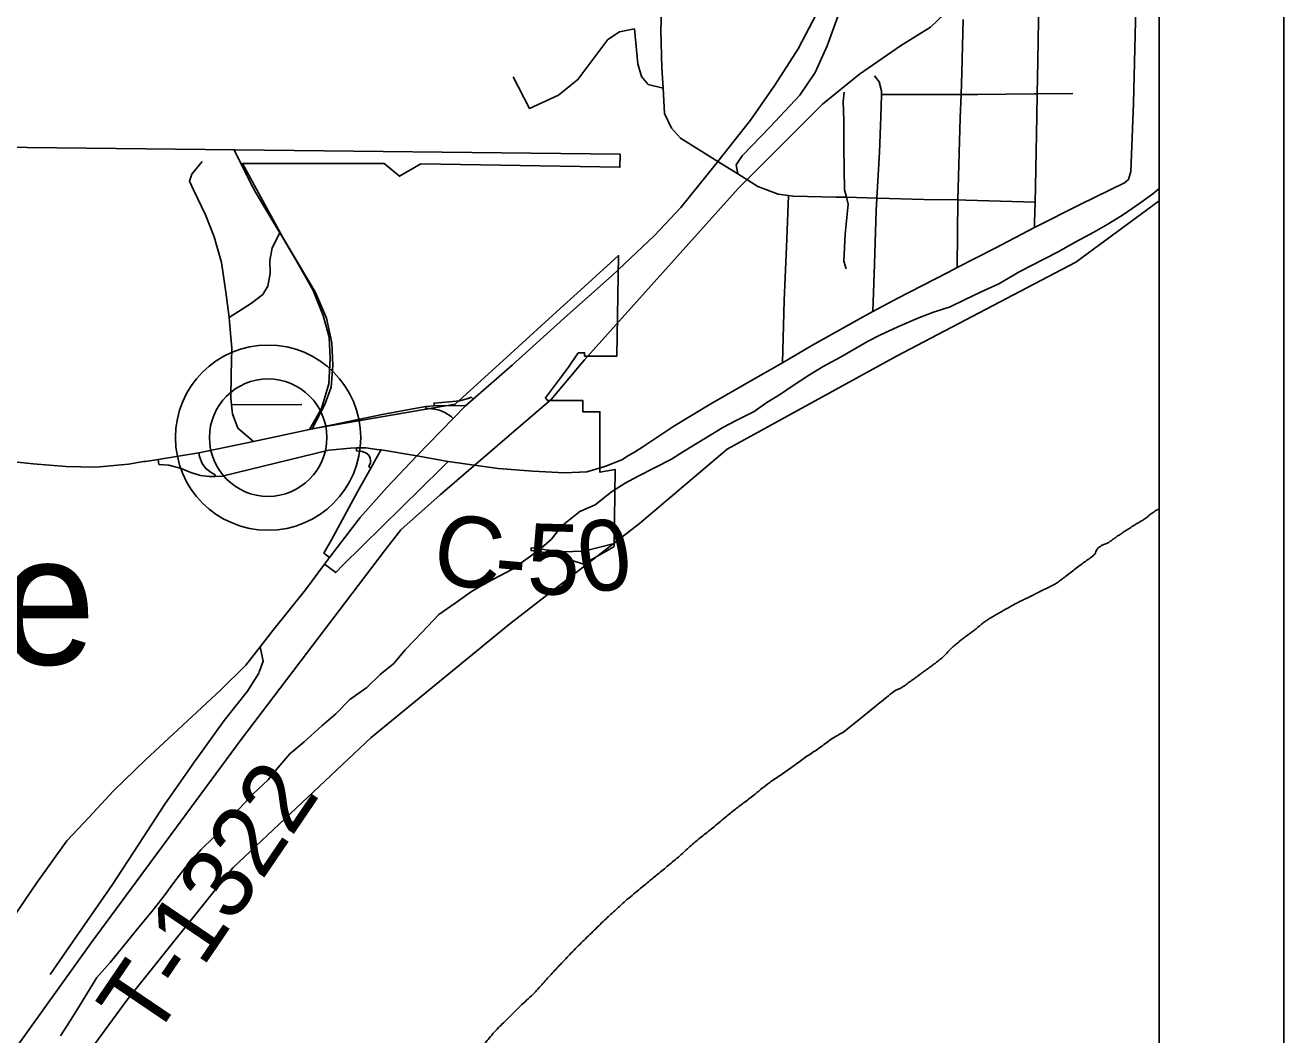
# Model space of a CAD drawing. Extents: x -84548 to 2262448, y -162180 to 525962.
# Drawn here: x 42243 to 47579, y 95098 to 99380 of the extents above; entities that cross this region are included whole.
import ezdxf

# ---------------------------------------------------------------- set-up
doc = ezdxf.new("R2010")
doc.units = 0
for name, color, linetype in [('GM_X_Adjacent_County_Text', 7, 'Continuous'), ('GM_X_County', 7, 'Continuous'), ('GM_X_County_Road', 7, 'Continuous'), ('GM_X_Hydro', 7, 'Continuous'), ('GM_X_Hydro_Text', 7, 'Continuous'), ('GM_X_Interstate_Location', 7, 'Continuous'), ('GM_X_Major_Lake_Text', 7, 'Continuous'), ('GM_X_Major_River', 7, 'Continuous'), ('GM_X_Minor_Lake', 7, 'Continuous'), ('GM_X_Minor_River_Text', 7, 'Continuous'), ('GM_X_Township_Road', 7, 'Continuous'), ('GM_X_Township_ROW', 7, 'Continuous'), ('GM_X_Township_Subdivision_Text', 7, 'Continuous'), ('GM_X_Unincorporated_Location', 7, 'Continuous'), ('GM_X_US_Location', 7, 'Continuous')]:
    doc.layers.add(name, color=color, linetype=linetype)

msp = doc.modelspace()

# ---------------------------------------------------------------- linework, layer by layer
at = {"layer": 'GM_X_County'}
for p, q in [((47578.7, 110848.8), (47578.7, 73888.8)), ((47050.7, 110320.8), (47050.7, 74416.8))]:
    msp.add_line(p, q, dxfattribs=at)
at = {"layer": 'GM_X_Hydro'}
for p, q in [((46697.6, 98375.1), (47050.7, 98634.4)), ((45936.2, 97976.2), (46697.6, 98375.1)), ((45218.9, 97582.1), (45936.2, 97976.2)), ((44847.3, 97266.3), (45218.9, 97582.1)), ((44297.1, 96841), (44847.3, 97266.3)), ((43709.8, 96358.8), (44297.1, 96841)), ((43123.7, 95806.4), (43709.8, 96358.8)), ((42676.3, 95246.3), (43123.7, 95806.4)), ((42168.9, 94556.7), (42676.3, 95246.3))]:
    msp.add_line(p, q, dxfattribs=at)
at = {"layer": 'GM_X_Hydro_Text'}
for points in [[(44142.4, 97793.9), (44133.4, 97802.5), (44117.5, 97795.1), (44084.5, 97787.3), (44042.6, 97782.3), (43976.8, 97776.9), (43977.6, 97765.4)], [(43941.2, 97762), (43941.5, 97755.2), (43978.8, 97751.7), (43999.5, 97746.6), (44022.6, 97737.2), (44048.4, 97720.7), (44058, 97711.3)], [(42806.8, 97538.1), (42810.1, 97516.9), (42852.8, 97514.5), (42904, 97500.3), (42945.7, 97483), (42986.5, 97470.6), (43023.3, 97465.1), (43048.8, 97466), (43077.8, 97466.9), (43531.2, 97578), (43622, 97586.6), (43648.4, 97586.7), (43687.8, 97586.9), (43744.2, 97579.3), (43752.1, 97578.2)], [(43648.4, 97586.7), (43648.3, 97574.2), (43672.3, 97572), (43687, 97566.6), (43700.1, 97556.2), (43705.6, 97544.2), (43707, 97534.5), (43706.6, 97523.5), (43700.4, 97508), (43709.1, 97501.7)], [(42979.5, 97566.6), (42982.2, 97550.2), (42993.2, 97520.5), (43008.9, 97499.3), (43031.4, 97482.1), (43048.6, 97472.7), (43048.8, 97466)], [(43752.1, 97578.2), (43743.5, 97565.4), (43724.6, 97529.3), (43709.1, 97501.7), (43653.7, 97402.9), (43541.7, 97197.2), (43509.2, 97140.9), (43533.7, 97122.8)], [(43512, 97093.5), (43559.6, 97058.3), (43589.5, 97089.2), (44006.8, 97499.3), (44037, 97530.1)]]:
    msp.add_lwpolyline(points, dxfattribs=at)
at = {"layer": 'GM_X_Interstate_Location'}
for points in [[(47050.7, 98686.8), (47023.5, 98665.1), (46972, 98628.2), (46898.8, 98576.9), (46833.3, 98535.7), (46773.8, 98502.6), (46696.4, 98461.3), (46619, 98417.9), (46460.1, 98335.1), (46370.8, 98283.5), (46293.3, 98248.2), (46227.7, 98217), (46164.1, 98185.9), (46094.4, 98162.7), (46034.7, 98139.7), (45943.2, 98100.1), (45865.7, 98064.7), (45814.1, 98037.8), (45699, 97971.8), (45625.5, 97932.5), (45568, 97897.4), (45498.7, 97852.2), (45445.2, 97815.2), (45387.7, 97780.2), (45334.2, 97741.2), (45256.7, 97703.9), (45201.2, 97672.9), (45131.7, 97631.6), (45034.6, 97571.9), (44983, 97538.9), (44913.5, 97503.7), (44842, 97466.5), (44786.4, 97437.5)], [(44786.4, 97437.5), (44728.9, 97400.4), (44659.7, 97345.2), (44594.1, 97318), (44517, 97254.6), (44473.8, 97199.7), (44420.5, 97152.7), (44365.1, 97113.7), (44309.7, 97072.7), (44198.5, 97014.7), (44135, 96977.6), (44065.7, 96928.3), (43996.4, 96881.1), (43925.5, 96805.7), (43854.6, 96730.4), (43805.4, 96673.4), (43748.1, 96626.3), (43690.9, 96571.2), (43619.7, 96519.9), (43560.6, 96458.8), (43501.3, 96407.7), (43426.3, 96340.3), (43365, 96289.1), (43313.9, 96230.1), (43272.7, 96179.3), (43209.5, 96120.1), (43150.5, 96057), (43075.5, 95989.6), (43044.3, 95936.9), (42989.1, 95883.9), (42922.2, 95806.5), (42873.2, 95743.6), (42832, 95686.7), (42781, 95621.7), (42731.9, 95562.7), (42604.2, 95404.2), (42547.2, 95341.1), (42516, 95290.4), (42473, 95221.5), (42434, 95156.7), (42392.9, 95093.9)]]:
    msp.add_lwpolyline(points, dxfattribs=at)
msp.add_open_spline([(45712.5, 96382.1), (45781, 96437.3), (45849.4, 96492.5), (45917.8, 96547.7), (45933.4, 96560.2), (45953.5, 96566.3), (45969.7, 96578), (45988.4, 96591.4), (46007, 96604.9), (46025.6, 96618.5), (46044.9, 96632.6), (46064.2, 96646.7), (46083.4, 96660.9), (46096.9, 96670.8), (46110.2, 96680.8), (46123.3, 96691.2), (46142.9, 96706.8), (46158.2, 96727.2), (46177.1, 96743.6), (46191.4, 96756.1), (46205.9, 96768.4), (46220.9, 96780), (46236.1, 96791.6), (46251.6, 96802.8), (46266.8, 96814.3), (46282.3, 96826.2), (46296.8, 96839.3), (46312.7, 96850.7), (46326, 96860.4), (46340.3, 96868.7), (46354.6, 96877), (46369.8, 96885.9), (46385.1, 96894.7), (46400.5, 96903.3), (46416.4, 96912.3), (46432.2, 96921.3), (46448.4, 96929.7), (46466.2, 96938.8), (46484.4, 96947), (46502.3, 96956), (46517, 96963.4), (46531.6, 96970.9), (46546.3, 96978.3), (46561.4, 96986), (46577.1, 96992.8), (46592.2, 97000.7), (46610.6, 97010.2), (46627.4, 97022.6), (46644.1, 97035), (46666.2, 97051.6), (46687.9, 97068.9), (46709.9, 97085.6), (46728.2, 97099.4), (46747.3, 97112.2), (46765.7, 97126), (46780.1, 97136.8), (46784.8, 97157.8), (46799.5, 97168.3), (46811.7, 97177), (46827.2, 97180.1), (46839.5, 97188.6), (46852.9, 97197.8), (46865.8, 97207.9), (46879.4, 97216.9), (46897.9, 97229.1), (46916.5, 97241.3), (46935.2, 97253.3), (46951.6, 97263.7), (46968.7, 97273.2), (46985.1, 97283.6), (47000.4, 97293.4), (47013.8, 97306), (47029, 97316), (47036, 97320.6), (47043.4, 97324.8), (47050.7, 97329)], degree=3, dxfattribs=at)
for points in [[(44891, 95751.7), (44930.9, 95784), (44974.7, 95820.4), (45024.5, 95862.8), (45066.4, 95901.1), (45110.2, 95937.4), (45158.1, 95975.8), (45211.9, 96020.3), (45253.8, 96054.6), (45293.6, 96084.9), (45337.5, 96119.2), (45399.3, 96167.7), (45443.2, 96198), (45523, 96254.6), (45568.9, 96287), (45616.7, 96319.3), (45666.6, 96355.7), (45712.5, 96382.1)], [(41241, 91094), (41262.8, 91144.3), (41286.6, 91184.6), (41320.3, 91228.9), (41360.1, 91271.2), (41381.9, 91311.4), (41421.8, 91349.8), (41445.6, 91394), (41481.3, 91454.4), (41497, 91494.6), (41530.8, 91544.9), (41582.5, 91605.4), (41616.3, 91645.7), (41672.1, 91698.2), (41715.9, 91744.5), (41743.7, 91788.8), (41785.4, 91837.2), (41821.2, 91883.5), (41847, 91927.8), (41906.6, 92018.4), (41944.3, 92076.8), (41976, 92131.1), (42005.7, 92183.4), (42027.5, 92223.7), (42057.3, 92276), (42081, 92318.2), (42106.8, 92360.5), (42136.6, 92414.8), (42196.1, 92515.4), (42225.8, 92563.7), (42253.6, 92606), (42287.3, 92658.4), (42315.1, 92698.6), (42336.9, 92740.9), (42370.7, 92789.2), (42400.5, 92831.5), (42434.2, 92889.8), (42470, 92940.2), (42507.7, 92996.6), (42543.4, 93044.9), (42575.2, 93089.2), (42607, 93131.5), (42636.8, 93173.8), (42664.6, 93216.1), (42692.4, 93256.3), (42726.2, 93302.7), (42754, 93342.9), (42793.7, 93401.3), (42823.5, 93441.6), (42855.3, 93481.9), (42891.1, 93522.2), (42926.9, 93572.5), (42974.7, 93627), (43008.4, 93669.3), (43048.2, 93723.7), (43087.9, 93774), (43153.5, 93862.6), (43185.3, 93906.9), (43231, 93965.4), (43266.8, 94009.7), (43316.6, 94068.1), (43358.3, 94114.5), (43410.1, 94171), (43449.9, 94213.3), (43479.7, 94253.6), (43521.6, 94277.9), (43563.5, 94318.2), (43611.3, 94354.6), (43653.2, 94392.9), (43720.8, 94463.5), (43764.7, 94499.9), (43808.5, 94550.3), (43852.2, 94604.7), (43884, 94653), (43929.6, 94721.4), (43967.4, 94769.8), (44033, 94858.4), (44076.7, 94910.8), (44110.5, 94955.1), (44140.3, 95001.4), (44176.1, 95041.7), (44209.9, 95084), (44255.7, 95134.4), (44295.5, 95172.7), (44335.3, 95213.1), (44389.1, 95263.5), (44432.9, 95309.9), (44472.7, 95354.2), (44512.5, 95396.6), (44558.3, 95445), (44606.1, 95493.4), (44655.9, 95541.8), (44705.7, 95590.2), (44747.5, 95628.6), (44787.3, 95664.9), (44845.1, 95713.3), (44891, 95751.7)]]:
    msp.add_spline(points, degree=3, dxfattribs=at)
at = {"layer": 'GM_X_Major_Lake_Text'}
for points in [[(44753.8, 98339.4), (44758.6, 98344), (44911.4, 98487.2), (45022.5, 98606.2), (45175.1, 98795.6), (45180.1, 98802), (45317.8, 98977), (45420.7, 99126), (45519.5, 99278.9), (45598.4, 99427.8), (45667, 99612.5), (45715.7, 99785.2), (45745.2, 99967.9), (45748.1, 99985.7), (45762.3, 100212.1), (45762.7, 100249), (45764.6, 100424.5), (45749.3, 100596.6), (45721.6, 100806.7), (45706.3, 100964.8), (45706, 100978), (45704.2, 101052.1), (45703.4, 101084.9), (45708.6, 101141.4)], [(44110.5, 97766), (44142.4, 97793.9), (44307.3, 97937.8), (44527.9, 98137.7), (44732.6, 98319.6), (44753.8, 98339.4)], [(41208.8, 97945.8), (41265.3, 97920.3), (41411.8, 97836.8), (41808.8, 97639.7), (41965.4, 97584.6), (42114.8, 97536.4), (42277.1, 97519.6), (42415.2, 97508.7), (42543.4, 97505.6), (42681.4, 97518.7), (42745.6, 97528.7), (42752.8, 97529.8)], [(42752.8, 97529.8), (42806.8, 97538.1), (42979.5, 97566.6), (43211.6, 97614.3), (43448.8, 97664.9), (43546.7, 97685.6), (43756.5, 97729.3), (43902.3, 97756.2), (43941.2, 97762), (43977.6, 97765.4), (44022.7, 97767.1), (44110.5, 97766)], [(43903.5, 97552.9), (44058, 97711.3), (44110.5, 97766)], [(43533.7, 97122.8), (43663.9, 97291.9), (43777, 97419), (43903.5, 97552.9)], [(43752.1, 97578.2), (43903.5, 97552.9), (44037, 97530.1)], [(41071.1, 93788.6), (41225.8, 94062.6), (41280.6, 94211.2), (41333.8, 94321.8), (41424.8, 94460.7), (41543.4, 94639.8), (41691.8, 94857.3), (41848.1, 95080.8), (41984.6, 95286.2), (42134.9, 95511.6), (42291.2, 95741.2), (42419.9, 95920.4), (42515.2, 96021.3), (42618.4, 96132.2), (42753.4, 96263.5), (42892.5, 96392.7), (43071.3, 96560.3), (43178.5, 96665.3), (43239.9, 96743.9), (43293.5, 96812.4), (43432.2, 96985.7), (43512, 97093.5), (43533.7, 97122.8)]]:
    msp.add_lwpolyline(points, dxfattribs=at)
at = {"layer": 'GM_X_Major_River'}
for radius in [392.8, 249]:
    msp.add_circle((43273.2, 97630.6), radius, dxfattribs=at)
at = {"layer": 'GM_X_Minor_Lake'}
for points in [[(43236.4, 96639.8), (43251.5, 96682.5), (43239.9, 96743.9)], [(42954.1, 96246.3), (42955.3, 96247.9), (42967.9, 96265.9), (43087, 96431), (43186.2, 96555.9), (43233.8, 96632.3), (43235.7, 96637.9), (43236.4, 96639.8)], [(42472.4, 95531.3), (42473.4, 95532.9), (42492.1, 95559.6), (42613, 95734.7), (42722.1, 95901.7), (42835, 96076.8), (42954.1, 96246.3)], [(42349.3, 95354.4), (42472.4, 95531.3)]]:
    msp.add_lwpolyline(points, dxfattribs=at)
at = {"layer": 'GM_X_Minor_River_Text'}
msp.add_lwpolyline([(44037, 97530.1), (44249, 97499.9), (44395.3, 97489), (44529.5, 97481.8), (44623.5, 97485.8), (44701.1, 97507.5), (44772.5, 97537), (44801.5, 97554.7)], dxfattribs=at)
at = {"layer": 'GM_X_Township_ROW'}
for points in [[(43215.8, 98679.5), (43200.6, 98705.6), (43129.7, 98850.7)], [(43108.7, 98139.9), (43093.9, 98248), (43075, 98374.1), (43044.2, 98482.1), (43007.5, 98576.1), (42956.7, 98681.9), (42940.5, 98717.9), (42950.2, 98748), (42993.9, 98802.4)], [(43448.8, 97664.9), (43499.7, 97753.8), (43531, 97858.2), (43536.2, 97966.4), (43531.5, 98056.5), (43506.8, 98148.5), (43464, 98254.5), (43401.2, 98368.3), (43338.4, 98474), (43323.2, 98499), (43271.6, 98583.8), (43216, 98679.2), (43215.8, 98679.5)], [(43211.6, 97614.3), (43144.2, 97671.3), (43121.7, 97731.3), (43118.1, 97769.2), (43115.2, 97799.4), (43116.5, 97897.5), (43119.7, 98009.8), (43113.2, 98071.8), (43108.7, 98139.9), (43202.3, 98200.7), (43250.1, 98237), (43271.8, 98273.2), (43281.4, 98327.4), (43281, 98381.5), (43290.6, 98435.7), (43323.2, 98499)], [(43118.1, 97769.2), (43415.5, 97771.3)]]:
    msp.add_lwpolyline(points, dxfattribs=at)
at = {"layer": 'GM_X_Township_Subdivision_Text'}
msp.add_lwpolyline([(41246.2, 98871.8), (44765.1, 98832.4), (44764.3, 98777.3), (43920.6, 98791.4), (43830, 98739), (43764.9, 98793.7), (43164.9, 98793.6), (43335.8, 98479.4), (43474.6, 98246.1), (43520, 98137.7), (43543.5, 98033.3), (43546.9, 97937.1), (43540.4, 97844.9), (43513.9, 97770.9), (43460.4, 97668.6), (43720.6, 97713.5), (44066, 97773), (44300.4, 97986.1), (44495.8, 98163.7), (44613.1, 98270.3), (44758.5, 98402.5), (44751.8, 97976.8), (44614.5, 97976.8), (44614.5, 97990.3), (44587.5, 97990.3), (44546.1, 97928.9), (44448.6, 97799.5), (44457.9, 97788.4), (44607.1, 97788.4), (44607.1, 97740.4), (44679.5, 97740.4), (44679.5, 97483.5), (44744.4, 97495.1), (44739.5, 97181.2), (44613.3, 97149), (44516.4, 97146), (44388.6, 97163.9), (44387.8, 97151.9), (44466, 97141), (44610.6, 97094), (44738.7, 97168), (44741.5, 97184.5), (44847.3, 97266.3), (45218.9, 97582.1), (45936.2, 97976.2), (46697.6, 98375.1), (47050.7, 98634.4), (47050.7, 109898.9)], dxfattribs=at)
at = {"layer": 'GM_X_Unincorporated_Location'}
for points in [[(45953.6, 99292.7), (46081.1, 99371.1), (46197.6, 99483.5), (46263.1, 99609.1), (46272, 99663.5), (46320, 101325.8), (46287.9, 101405.9), (46163.8, 101688.7), (46110.4, 101854), (46059.5, 102031), (46017.3, 102132.8), (45944.3, 102204.4), (44999.2, 103131.7), (44132.9, 103939.2)], [(40921.8, 93255), (42522.6, 95488.3), (43158.2, 96349.8), (43766.5, 97151), (43836.3, 97239.1), (44001.9, 97387.6), (44365.8, 97699.9), (44473.2, 97792.2), (44613.7, 97960.7), (45265, 98686.9), (45623.6, 99044.3), (45780.2, 99172.7), (45953.6, 99292.7)]]:
    msp.add_lwpolyline(points, dxfattribs=at)
at = {"layer": 'GM_X_US_Location'}
for points in [[(45264.9, 98749.2), (45180.1, 98802), (45021.1, 98901.1), (44982.6, 98942.8), (44953.9, 99004.7), (44947.3, 99112.6), (44941.9, 99199), (44938.3, 99357.2), (44941.4, 99439.4), (44966.4, 99543.9), (45028.3, 99752.9), (45078.6, 99919.7), (45109.2, 100054.3), (45137.7, 100206.9), (45148.3, 100337.3), (45152.9, 100475.6), (45141.7, 100593.7), (45122.5, 100705.8), (45081.1, 100837.6), (45023.7, 100971.3), (44974.8, 101049)], [(46522, 98525.8), (46522.4, 98542.5), (46524.6, 98629), (46526.2, 98694), (46531.7, 98994.6), (46533.7, 99088.2), (46536.6, 99227.1), (46539.3, 99400.5), (46540, 99441.5), (46544.7, 99686), (46545.7, 99731.4), (46549.8, 99912.4), (46549.6, 100090.2), (46549.6, 100102.7), (46560.1, 100451.5), (46568.8, 100788.2), (46597.1, 100787.4)], [(46920.6, 98725.3), (46930.2, 98759.4), (46941.2, 99048.1), (46949.7, 99397), (46958.8, 99669.5), (46966.6, 99890), (46973.9, 100077.5), (46977.7, 100172.7), (46988.1, 100515.5), (47050.7, 100643.8)], [(45264.9, 98749.2), (45256.5, 98787.2), (45282.1, 98825.5), (45400.9, 98948.9), (45527.6, 99082.4), (45592.7, 99179.3), (45643.6, 99292), (45687.7, 99416.2), (45692.2, 99428.7), (45734.5, 99597.5), (45775, 99746.2)], [(46194.4, 98352.1), (46196.8, 98638.8), (46207.2, 98986.9), (46210.3, 99085.8), (46213.2, 99179.3), (46218.9, 99404.5)], [(44311.8, 99160.7), (44381.2, 99027.1), (44504.7, 99082.5), (44586.1, 99149.4), (44649.3, 99234.2), (44712.5, 99319), (44762.2, 99351.5), (44826.1, 99364.2), (44839.7, 99216), (44856.2, 99162.1), (44884.6, 99128.3), (44947.3, 99112.6)], [(45870.7, 98993.8), (45872.4, 99035.7), (45873.4, 99085.9), (45873.7, 99101.8), (45863.3, 99139.8), (45843.1, 99165.7)], [(45720.2, 98666.1), (45720.1, 98666.5), (45716, 98681.5), (45714.1, 98861.8), (45712.9, 98976), (45710.1, 99056.2), (45715.7, 99096.3)], [(45873.4, 99085.9), (46090.1, 99085.9), (46210.3, 99085.8), (46282.3, 99085.8), (46522.5, 99088.1), (46533.7, 99088.2), (46684.6, 99089.7)], [(45836.7, 98165.1), (45843.3, 98366.1), (45851, 98594.6), (45853.8, 98646.8), (45864.4, 98841.2), (45870.6, 98990.5), (45870.7, 98993.8)], [(45264.9, 98749.2), (45349.5, 98695.9), (45435.9, 98662.7), (45478.6, 98657.6), (45498, 98655.3), (45499.3, 98655.3)], [(46483.9, 98501.6), (46521.9, 98521.7), (46715.5, 98619.1), (46902.7, 98711.1), (46920.6, 98725.3)], [(45453, 97948.4), (45460.6, 98212), (45471.9, 98472.7), (45478.6, 98657.6)], [(45499.3, 98655.3), (45680.2, 98651), (45724.7, 98650), (45853.8, 98646.8), (45856.4, 98646.8), (46052.7, 98640.7), (46196.8, 98638.8), (46230.9, 98638.4), (46524.6, 98629)], [(45723.4, 98346.9), (45713.1, 98378.8), (45719.9, 98493.1), (45732.6, 98621.5), (45724.7, 98650), (45720.2, 98666.1)], [(44801.5, 97554.7), (44825.8, 97569.4), (44861.3, 97591), (44993.5, 97679.9), (45149.5, 97773.4), (45359, 97894), (45453, 97948.4), (45578.3, 98020.9), (45770.1, 98129.1), (45836.7, 98165.1), (45940.2, 98220.9), (46153.9, 98331.6), (46194.4, 98352.1), (46355.7, 98434), (46521.9, 98521.7), (46522, 98525.8)]]:
    msp.add_lwpolyline(points, dxfattribs=at)

# ---------------------------------------------------------------- texts
at = {"layer": 'GM_X_Adjacent_County_Text'}
msp.add_text('Springdale', height=550, rotation=0, dxfattribs=at).set_placement((39026.7, 96668.3))
at = {"layer": 'GM_X_County_Road'}
for s, rotation, p in [('C', 350.7526, (43957.6, 97022.3)), ('5', 358.5384, (44367.8, 96967.8)), ('0', 8.6545, (44610.2, 96966.7)), ('-', 355.0011, (44224.9, 96979.7))]:
    msp.add_text(s, height=300, rotation=rotation, dxfattribs=at).set_placement(p)
at = {"layer": 'GM_X_Township_Road'}
msp.add_text('T-1322', height=300, rotation=55.8606, dxfattribs=at).set_placement((42783.1, 95065.9))

doc.saveas('drawing.dxf')
